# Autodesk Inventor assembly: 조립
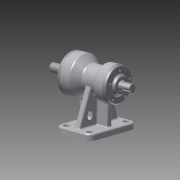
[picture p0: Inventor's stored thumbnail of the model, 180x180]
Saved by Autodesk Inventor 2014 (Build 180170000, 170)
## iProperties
Created: 2015-08
Part Number: 조립
Document SubType Name: Assembly
Designer: Owner
Author: Owner
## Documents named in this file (10)
- C:\Documents and Settings\Owner\바탕 화면\450805V1005\조립.iam
- C:\Documents and Settings\Owner\바탕 화면\450805V1005\축.ipt
- C:\Documents and Settings\Owner\바탕 화면\450805V1005\베어링 6203.ipt
- C:\Documents and Settings\Owner\바탕 화면\450805V1005\베어링 6205.ipt
- C:\Documents and Settings\Owner\바탕 화면\450805V1005\뒤커버.ipt
- C:\Documents and Settings\Owner\바탕 화면\450805V1005\앞커버.ipt
- C:\Documents and Settings\Owner\바탕 화면\450805V1005\본체.ipt
- C:\Documents and Settings\Owner\바탕 화면\450805V1005\오일실 .ipt
- 오일실 .ipt
- C:\Documents and Settings\Owner\바탕 화면\450805V1005\M4x0.5.ipt
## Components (10 placed, 1 different names)
1. M4x0.5:1
2. M4x0.5:2
3. M4x0.5:3
4. M4x0.5:4
5. M4x0.5:5
6. M4x0.5:6
7. M4x0.5:7
8. M4x0.5:8
9. M4x0.5:9
10. M4x0.5:10
